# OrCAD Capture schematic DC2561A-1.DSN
size B; title: DUAL WIDE RANGE I2C POWER MONITOR; rev: 1; note: DEMO CIRCUIT 2561A
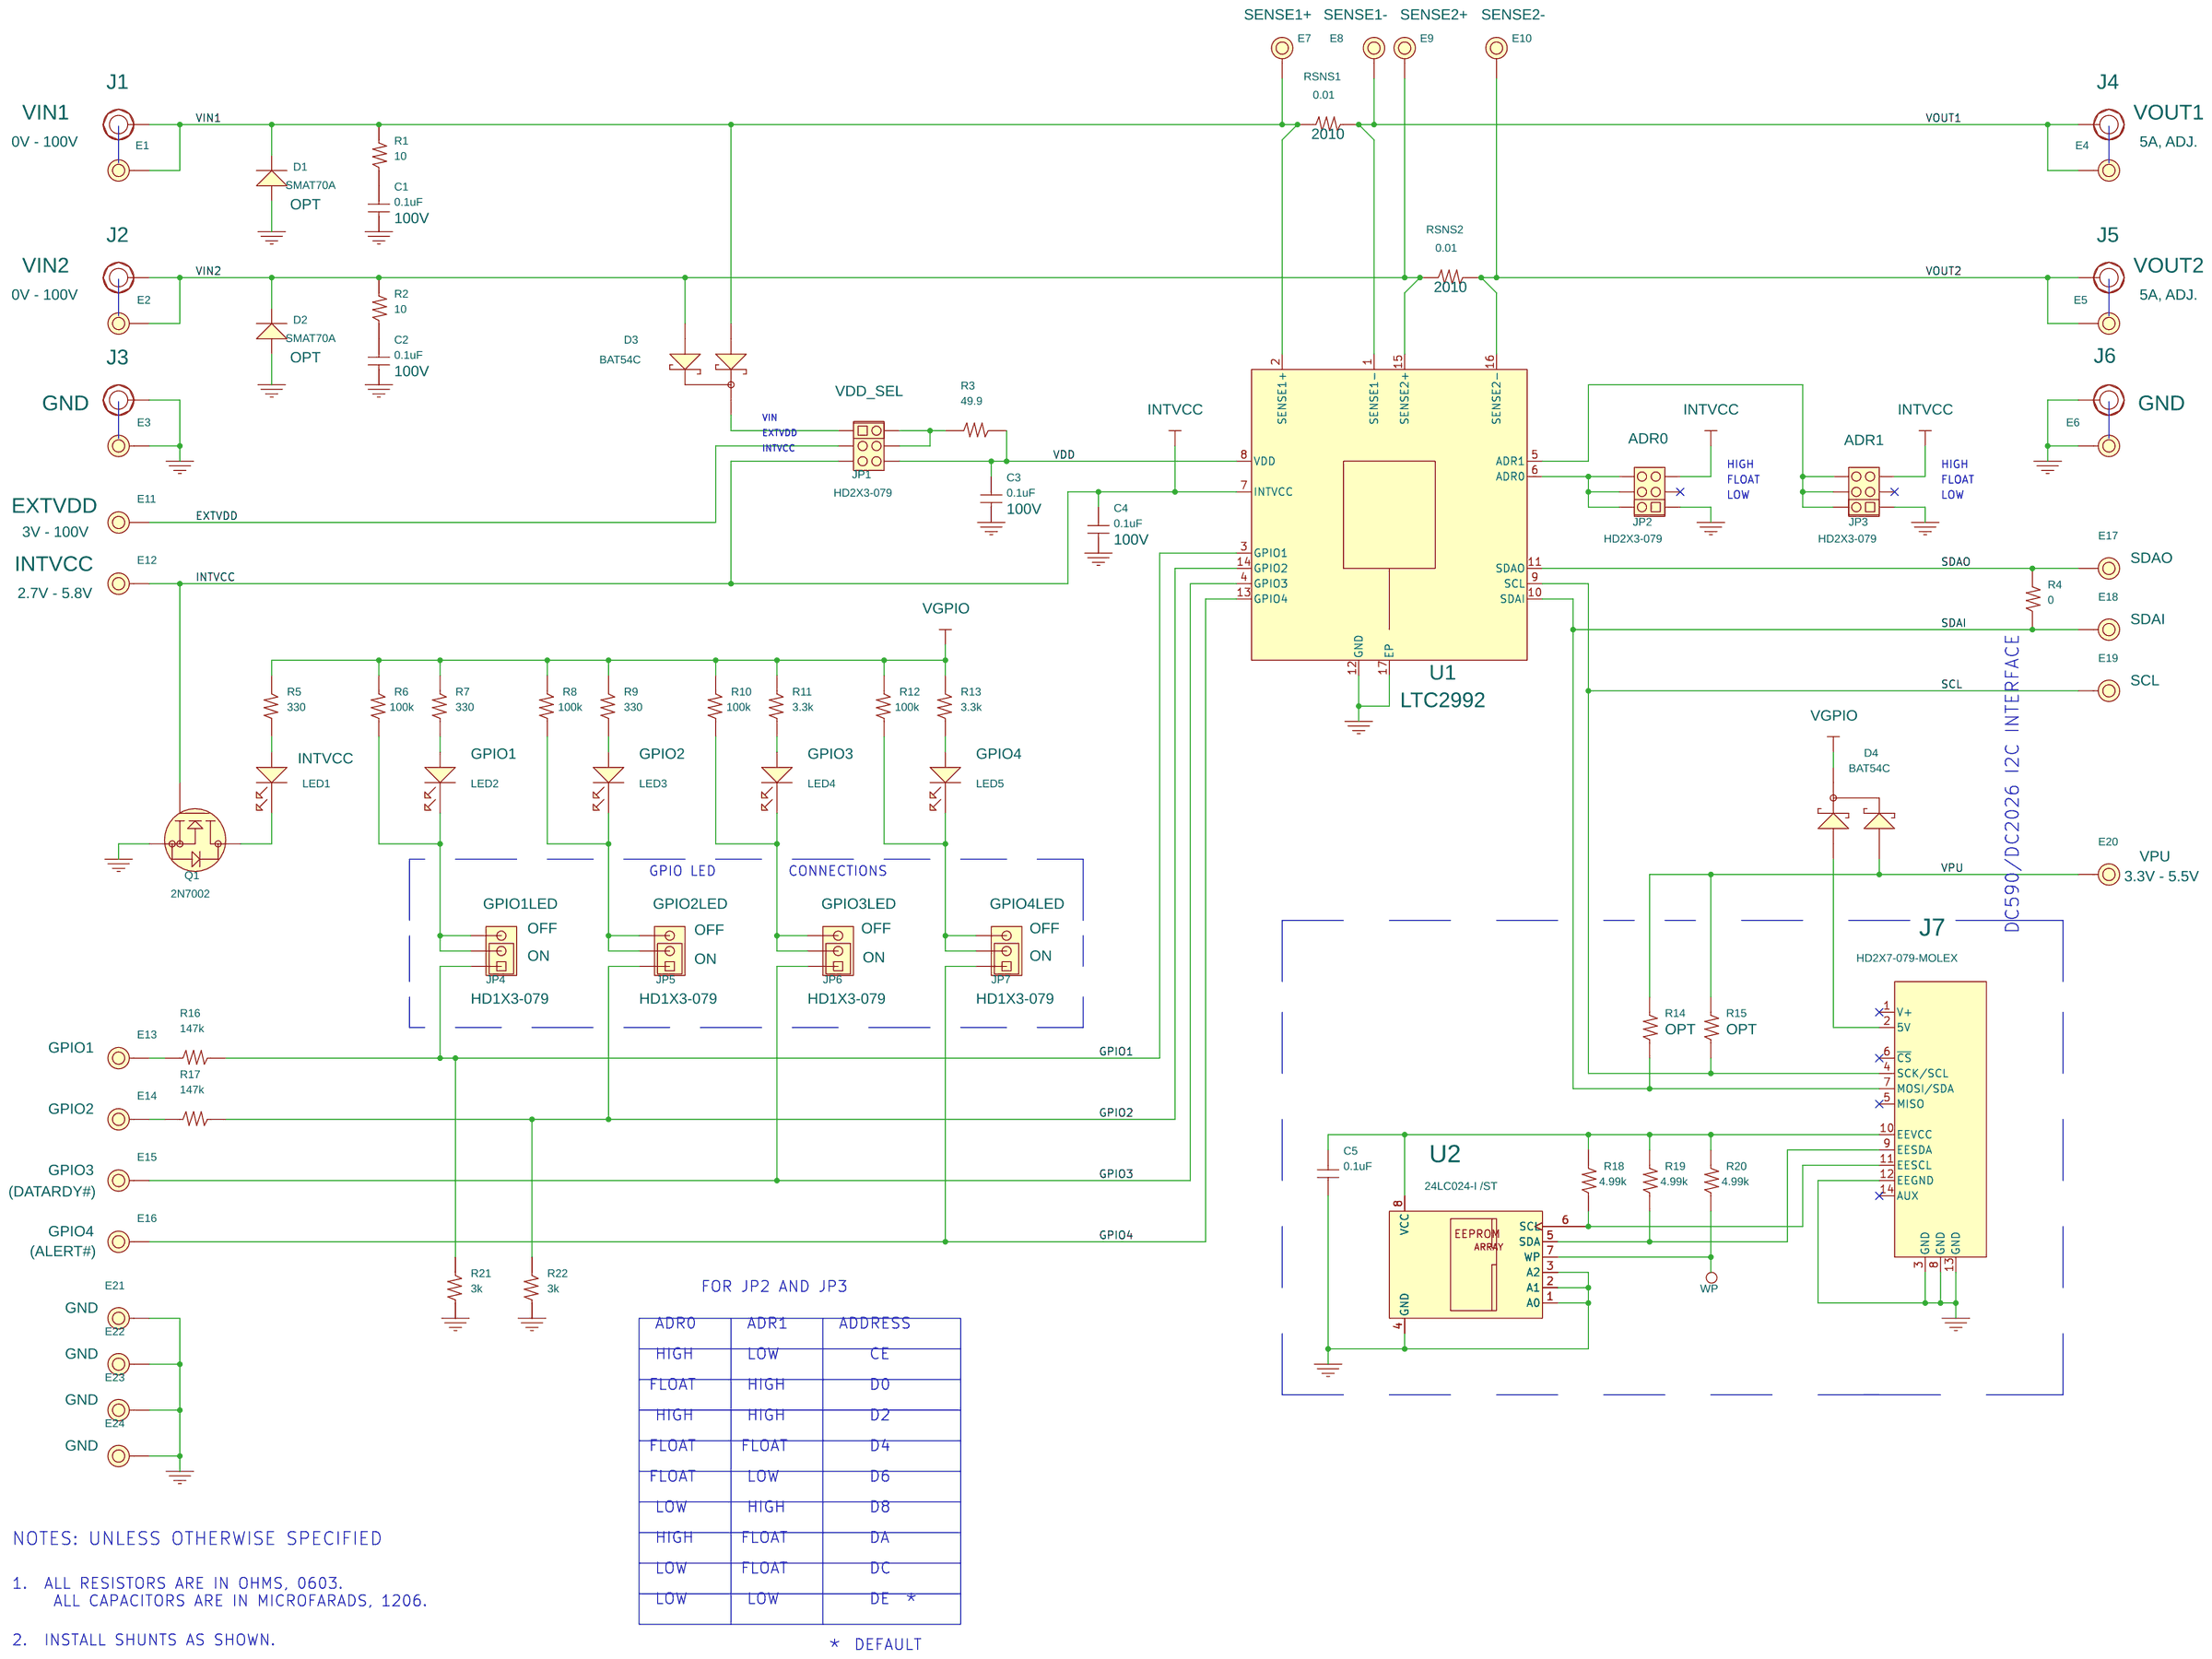
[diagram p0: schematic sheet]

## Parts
C1  0.1uF  [1206]
C2  0.1uF  [1206]
C3  0.1uF  [1206]
C4  0.1uF  [1206]
C5  0.1uF  [1206]
D1  SMAT70A  [SMA-DIODE]
D2  SMAT70A  [SMA-DIODE]
D3  BAT54C  [SOT23]
D4  BAT54C  [SOT23]
E1  MIL-MAX-2308  [MILL-MAX-2308]
E2  MIL-MAX-2308  [MILL-MAX-2308]
E3  MIL-MAX-2308  [MILL-MAX-2308]
E4  MIL-MAX-2308  [MILL-MAX-2308]
E5  MIL-MAX-2308  [MILL-MAX-2308]
E6  MIL-MAX-2308  [MILL-MAX-2308]
E7  MIL-MAX-2308  [MILL-MAX-2308]
E8  MIL-MAX-2308  [MILL-MAX-2308]
E9  MIL-MAX-2308  [MILL-MAX-2308]
E10  MIL-MAX-2308  [MILL-MAX-2308]
E11  MIL-MAX-2308  [MILL-MAX-2308]
E12  MIL-MAX-2308  [MILL-MAX-2308]
E13  MIL-MAX-2308  [MILL-MAX-2308]
E14  MIL-MAX-2308  [MILL-MAX-2308]
E15  MIL-MAX-2308  [MILL-MAX-2308]
E16  MIL-MAX-2308  [MILL-MAX-2308]
E17  MIL-MAX-2308  [MILL-MAX-2308]
E18  MIL-MAX-2308  [MILL-MAX-2308]
E19  MIL-MAX-2308  [MILL-MAX-2308]
E20  MIL-MAX-2308  [MILL-MAX-2308]
E21  MIL-MAX-2308  [MILL-MAX-2308]
E22  MIL-MAX-2308  [MILL-MAX-2308]
E23  MIL-MAX-2308  [MILL-MAX-2308]
E24  MIL-MAX-2308  [MILL-MAX-2308]
J1  KEY-575  [KEY-575]
J2  KEY-575  [KEY-575]
J3  KEY-575  [KEY-575]
J4  KEY-575  [KEY-575]
J5  KEY-575  [KEY-575]
J6  KEY-575  [KEY-575]
J7  HD2X7-079-MOLEX  [HD2X7-079-MOLEX]
JP1  HD2X3-079  [HD2X3-079]
JP2  HD2X3-079  [HD2X3-079]
JP3  HD2X3-079  [HD2X3-079]
JP4  HD1X3-079  [HD1X3-079]
JP5  HD1X3-079  [HD1X3-079]
JP6  HD1X3-079  [HD1X3-079]
JP7  HD1X3-079  [HD1X3-079]
LED1  SML-012P8T  [LED-ROHM-SML-01]
LED2  SML-012P8T  [LED-ROHM-SML-01]
LED3  SML-012P8T  [LED-ROHM-SML-01]
LED4  SML-012Y8T  [LED-ROHM-SML-01]
LED5  SML-012V8T  [LED-ROHM-SML-01]
Q1  2N7002  [SOT23]
R1  10  [0603]
R2  10  [0603]
R3  49.9  [0603]
R4  0  [0603]
R5  330  [0603]
R6  100k  [0603]
R7  330  [0603]
R8  100k  [0603]
R9  330  [0603]
R10  100k  [0603]
R11  3.3k  [0603]
R12  100k  [0603]
R13  3.3k  [0603]
R14  R-0603  [0603]
R15  R-0603  [0603]
R16  147k  [0603]
R17  147k  [0603]
R18  4.99k  [0603]
R19  4.99k  [0603]
R20  4.99k  [0603]
R21  3k  [0603]
R22  3k  [0603]
RSNS1  0.01  [2512-2010]
RSNS2  0.01  [2512-2010]
U1  LTC2992  [DFN16DE-4X3]
U2  24LC024-I /ST  [TSSOP8]
WP  E-SMT-060  [PAD060-SMT-T]

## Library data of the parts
C1-C5 = CAP-NP: VOLTAGE: 100V
D1 D2 = DIODE-SMAT70A-SMA-DIODE: OPT: OPT
D3 D4 = BAT54C
E1-E6 = E-064
E7 = E-064: 1ST PART FIELD: SENSE1+
E8 = E-064: 1ST PART FIELD: SENSE1-
E9 = E-064: 1ST PART FIELD: SENSE2+
E10 = E-064: 1ST PART FIELD: SENSE2-
E11 = E-064: 1ST PART FIELD: EXTVDD; 2ND PART FIELD: 3V - 100V
E12 = E-064: 1ST PART FIELD: INTVCC; 2ND PART FIELD: 2.7V - 5.8V
E13 = E-064: 1ST PART FIELD: GPIO1
E14 = E-064: 1ST PART FIELD: GPIO2
E15 = E-064: 1ST PART FIELD: GPIO3; 2ND PART FIELD: (DATARDY#)
E16 = E-064: 1ST PART FIELD: GPIO4; 2ND PART FIELD: (ALERT#)
E17 = E-064: 1ST PART FIELD: SDAO
E18 = E-064: 1ST PART FIELD: SDAI
E19 = E-064: 1ST PART FIELD: SCL
E20 = E-064: 1ST PART FIELD: VPU; 2ND PART FIELD: 3.3V - 5.5V
E21-E24 = E-064: 1ST PART FIELD: GND
J1 = E-KEY-575: 1ST PART FIELD: 0V - 100V; FUNTION: VIN1
J2 = E-KEY-575: 1ST PART FIELD: 0V - 100V; FUNTION: VIN2
J3 J6 = E-KEY-575: FUNTION: GND
J4 = E-KEY-575: 1ST PART FIELD: 5A, ADJ.; FUNTION: VOUT1
J5 = E-KEY-575: 1ST PART FIELD: 5A, ADJ.; FUNTION: VOUT2
J7 = HD2X7-079-MOLEX
JP1 = HD2X3-079_1: 1ST PART FIELD: VDD_SEL
JP2 = HD2X3-079_1: 1ST PART FIELD: ADR0
JP3 = HD2X3-079_1: 1ST PART FIELD: ADR1
JP4 = HD1X3: 1ST PART FIELD: GPIO1LED; 2ND PART FIELD: ON; 3RD PART FIELD: OFF
JP5 = HD1X3: 1ST PART FIELD: GPIO2LED; 2ND PART FIELD: ON; 3RD PART FIELD: OFF
JP6 = HD1X3: 1ST PART FIELD: GPIO3LED; 2ND PART FIELD: ON; 3RD PART FIELD: OFF
JP7 = HD1X3: 1ST PART FIELD: GPIO4LED; 2ND PART FIELD: ON; 3RD PART FIELD: OFF
LED1 = LED-ROHM-SML-012P8TT86-GREEN: 1ST PART FIELD: INTVCC
LED2 = LED-ROHM-SML-012P8TT86-GREEN: 1ST PART FIELD: GPIO1; 2ND PART FIELD: (LOW)
LED3 = LED-ROHM-SML-012P8TT86-GREEN: 1ST PART FIELD: GPIO2; 2ND PART FIELD: (LOW)
LED4 = LED-ROHM-SML-012Y8TT86-YELLOW: 1ST PART FIELD: GPIO3
LED5 = LED-ROHM-SML-012V8TT86-RED: 1ST PART FIELD: GPIO4
Q1 = MOSFET_N-2N7002-SOT23
R1-R13 R16-R22 = R
R14 R15 = R: OPT: OPT
RSNS1 RSNS2 = R: 1ST PART FIELD: 2010
U1 = LTC2992IDE-DFN16DE-4X3
U2 = 24LC025-I_ST
WP = E-SMT-060

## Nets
GND: C1.2 C2.2 C3.2 C4.2 C5.1 D1.2 D2.2 E3.1(A) E6.1(A) E21.1(A) E22.1(A) E23.1(A) E24.1(A) J3.1 J6.1 J7.3(GND) J7.8(GND) J7.12(EEGND) J7.13(GND) JP2.1 JP3.1 Q1.2 R21.2 R22.2 U1.12(GND) U1.17(EP) U2.1(A0) U2.2(A1) U2.3(A2) U2.4(GND)
VDD: C3.1 JP1.6 R3.1 U1.8(VDD)
VIN1: D1.1 D3.1 E1.1(A) E7.1(A) J1.1 R1.2 RSNS1.2 U1.2(SENSE1+)
VIN2: D2.1 D3.2 E2.1(A) E9.1(A) J2.1 R2.2 RSNS2.2 U1.15(SENSE2+)
EXTVDD: E11.1(A) JP1.3
GPIO1: JP4.1 R16.1 R21.1 U1.3(GPIO1)
GPIO2: JP5.1 R17.1 R22.1 U1.14(GPIO2)
GPIO3: E15.1(A) JP6.1 U1.4(GPIO3)
GPIO4: E16.1(A) JP7.1 U1.13(GPIO4)
INTVCC: C4.1 E12.1(A) JP1.5 JP2.5 JP3.5 Q1.1 U1.7(INTVCC)
SCL: E19.1(A) J7.4(SCK/SCL) R15.1 U1.9(SCL)
SDAI: E18.1(A) J7.7(MOSI/SDA) R4.1 R14.1 U1.10(SDAI)
SDAO: E17.1(A) R4.2 U1.11(SDAO)
VGPIO: D4.3 R5.1 R6.1 R7.1 R8.1 R9.1 R10.1 R11.1 R12.1 R13.1
VOUT1: E4.1(A) E8.1(A) J4.1 RSNS1.1 U1.1(SENSE1-)
VOUT2: E5.1(A) E10.1(A) J5.1 RSNS2.1 U1.16(SENSE2-)
VPU: D4.2 E20.1(A) R14.2 R15.2
N49597: JP2.2 JP2.4 JP2.6 U1.6(ADR0)
N49659: JP3.2 JP3.4 JP3.6 U1.5(ADR1)
N16106555: C5.2 J7.10(EEVCC) R18.2 R19.2 R20.2 U2.8(VCC)
N16106575: J7.9(EESDA) R19.1 U2.5(SDA)
N16106615: R20.1 U2.7(WP) WP.1
N16106721: J7.11(EESCL) R18.1 U2.6(SCL)
N16110333: D4.1 J7.2(5V)
N16115985: JP1.2 JP1.4 R3.2
N16116598: E13.1(A) R16.2
N16116646: E14.1(A) R17.2
N16117432: JP4.2 JP4.3 LED2.2 R6.2
N16117499: LED2.1 R7.2
N16118449: JP5.2 JP5.3 LED3.2 R8.2
N16118493: LED3.1 R9.2
N16118683: JP6.2 JP6.3 LED4.2 R10.2
N16118727: LED4.1 R11.2
N16118917: JP7.2 JP7.3 LED5.2 R12.2
N16118961: LED5.1 R13.2
N16121874: LED1.1 R5.2
N16121927: LED1.2 Q1.3
N16128238: D3.3 JP1.1
N16142397: C1.1 R1.1
N16142398: C2.1 R2.1

Not connected (* = marked no-connect by the designer): J7 1(V+)* 5(MISO)* 6(~{CS})* 14(AUX)*; JP2 3*; JP3 3*

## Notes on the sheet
- VIN
- EXTVDD
- INTVCC
- HIGH
- HIGH
- FLOAT
- FLOAT
- LOW
- LOW
- GPIO LED
- CONNECTIONS
- DC590/DC2026 I2C INTERFACE
- FOR JP2 AND JP3
- ADR0
- ADR1
- ADDRESS
- HIGH
- LOW
- CE
- FLOAT
- HIGH
- D0
- HIGH
- HIGH
- D2
- FLOAT
- FLOAT
- D4
- FLOAT
- LOW
- D6
- LOW
- HIGH
- D8
- NOTES: UNLESS OTHERWISE SPECIFIED
- HIGH
- FLOAT
- DA
- LOW
- FLOAT
- DC
- 1.  ALL RESISTORS ARE IN OHMS, 0603.
       ALL CAPACITORS ARE IN MICROFARADS, 1206.
- LOW
- LOW
- DE
- *
- 2.  INSTALL SHUNTS AS SHOWN.
- *
- DEFAULT
